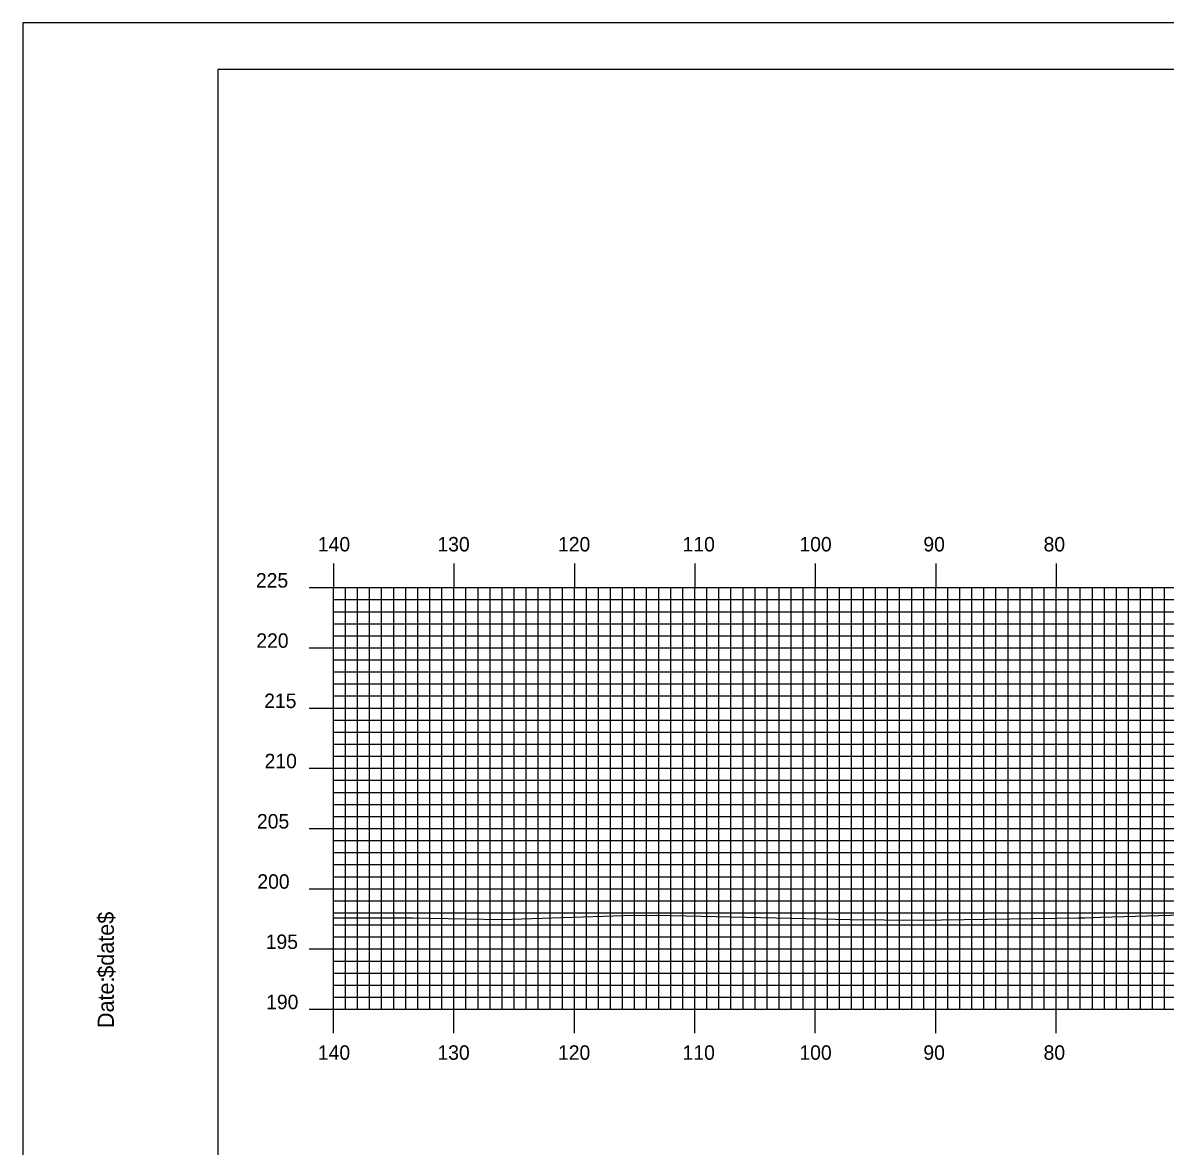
# Model space of a CAD drawing. Extents: x 1811374 to 1811717, y 442591 to 442811.
# Drawn here: x 1811373.6 to 1811468.4, y 442717.3 to 442810.5 of the extents above; entities that cross this region are included whole.
import ezdxf

# ---------------------------------------------------------------- set-up
doc = ezdxf.new("R2010")
doc.units = 0
for name, color, linetype in [('BORDER', 7, 'Continuous'), ('H_V ANNOTATION', 7, 'Continuous'), ('MAJOR', 7, 'Continuous'), ('MINOR', 7, 'Continuous'), ('PLOT BOUNDARY', 7, 'Continuous'), ('S_Roadway_Centerline', 7, 'Continuous')]:
    doc.layers.add(name, color=color, linetype=linetype)

msp = doc.modelspace()

# ---------------------------------------------------------------- linework, layer by layer
at = {"layer": 'BORDER'}
msp.add_lwpolyline([(1811389.803, 442596.665), (1811709.803, 442596.665), (1811709.803, 442806.665), (1811389.803, 442806.665)], close=True, dxfattribs=at)
at = {"layer": 'MAJOR'}
for p, q in [((1811399.403, 442765.669), (1811399.403, 442763.665)), ((1811409.403, 442765.669), (1811409.403, 442763.665)), ((1811419.403, 442765.669), (1811419.403, 442763.665)), ((1811429.403, 442765.669), (1811429.403, 442763.665)), ((1811439.403, 442765.669), (1811439.403, 442763.665)), ((1811449.403, 442765.669), (1811449.403, 442763.665)), ((1811459.403, 442765.669), (1811459.403, 442763.665)), ((1811397.399, 442763.665), (1811399.403, 442763.665)), ((1811399.403, 442763.665), (1811679.403, 442763.665)), ((1811399.403, 442728.665), (1811399.403, 442763.665)), ((1811399.403, 442728.665), (1811399.403, 442763.665)), ((1811399.403, 442763.665), (1811679.403, 442763.665)), ((1811409.403, 442728.665), (1811409.403, 442763.665)), ((1811419.403, 442728.665), (1811419.403, 442763.665)), ((1811429.403, 442728.665), (1811429.403, 442763.665)), ((1811439.403, 442728.665), (1811439.403, 442763.665)), ((1811449.403, 442728.665), (1811449.403, 442763.665)), ((1811459.403, 442728.665), (1811459.403, 442763.665)), ((1811397.399, 442758.665), (1811399.403, 442758.665)), ((1811399.403, 442758.665), (1811679.403, 442758.665)), ((1811397.399, 442753.665), (1811399.403, 442753.665)), ((1811399.403, 442753.665), (1811679.403, 442753.665)), ((1811397.399, 442748.665), (1811399.403, 442748.665)), ((1811399.403, 442748.665), (1811679.403, 442748.665)), ((1811397.399, 442743.665), (1811399.403, 442743.665)), ((1811399.403, 442743.665), (1811679.403, 442743.665)), ((1811397.399, 442738.665), (1811399.403, 442738.665)), ((1811399.403, 442738.665), (1811679.403, 442738.665)), ((1811397.399, 442733.665), (1811399.403, 442733.665)), ((1811399.403, 442733.665), (1811679.403, 442733.665)), ((1811397.399, 442728.665), (1811399.403, 442728.665)), ((1811399.403, 442728.665), (1811679.403, 442728.665)), ((1811399.403, 442728.665), (1811679.403, 442728.665)), ((1811399.403, 442726.661), (1811399.403, 442728.665)), ((1811409.403, 442726.661), (1811409.403, 442728.665)), ((1811419.403, 442726.661), (1811419.403, 442728.665)), ((1811429.403, 442726.661), (1811429.403, 442728.665)), ((1811439.403, 442726.661), (1811439.403, 442728.665)), ((1811449.403, 442726.661), (1811449.403, 442728.665)), ((1811459.403, 442726.661), (1811459.403, 442728.665))]:
    msp.add_line(p, q, dxfattribs=at)
at = {"layer": 'MINOR'}
for p, q in [((1811400.403, 442728.665), (1811400.403, 442763.665)), ((1811401.403, 442728.665), (1811401.403, 442763.665)), ((1811402.403, 442728.665), (1811402.403, 442763.665)), ((1811403.403, 442728.665), (1811403.403, 442763.665)), ((1811404.403, 442728.665), (1811404.403, 442763.665)), ((1811405.403, 442728.665), (1811405.403, 442763.665)), ((1811406.403, 442728.665), (1811406.403, 442763.665)), ((1811407.403, 442728.665), (1811407.403, 442763.665)), ((1811408.403, 442728.665), (1811408.403, 442763.665)), ((1811410.403, 442728.665), (1811410.403, 442763.665)), ((1811411.403, 442728.665), (1811411.403, 442763.665)), ((1811412.403, 442728.665), (1811412.403, 442763.665)), ((1811413.403, 442728.665), (1811413.403, 442763.665)), ((1811414.403, 442728.665), (1811414.403, 442763.665)), ((1811415.403, 442728.665), (1811415.403, 442763.665)), ((1811416.403, 442728.665), (1811416.403, 442763.665)), ((1811417.403, 442728.665), (1811417.403, 442763.665)), ((1811418.403, 442728.665), (1811418.403, 442763.665)), ((1811420.403, 442728.665), (1811420.403, 442763.665)), ((1811421.403, 442728.665), (1811421.403, 442763.665)), ((1811422.403, 442728.665), (1811422.403, 442763.665)), ((1811423.403, 442728.665), (1811423.403, 442763.665)), ((1811424.403, 442728.665), (1811424.403, 442763.665)), ((1811425.403, 442728.665), (1811425.403, 442763.665)), ((1811426.403, 442728.665), (1811426.403, 442763.665)), ((1811427.403, 442728.665), (1811427.403, 442763.665)), ((1811428.403, 442728.665), (1811428.403, 442763.665)), ((1811430.403, 442728.665), (1811430.403, 442763.665)), ((1811431.403, 442728.665), (1811431.403, 442763.665)), ((1811432.403, 442728.665), (1811432.403, 442763.665)), ((1811433.403, 442728.665), (1811433.403, 442763.665)), ((1811434.403, 442728.665), (1811434.403, 442763.665)), ((1811435.403, 442728.665), (1811435.403, 442763.665)), ((1811436.403, 442728.665), (1811436.403, 442763.665)), ((1811437.403, 442728.665), (1811437.403, 442763.665)), ((1811438.403, 442728.665), (1811438.403, 442763.665)), ((1811440.403, 442728.665), (1811440.403, 442763.665)), ((1811441.403, 442728.665), (1811441.403, 442763.665)), ((1811442.403, 442728.665), (1811442.403, 442763.665)), ((1811443.403, 442728.665), (1811443.403, 442763.665)), ((1811444.403, 442728.665), (1811444.403, 442763.665)), ((1811445.403, 442728.665), (1811445.403, 442763.665)), ((1811446.403, 442728.665), (1811446.403, 442763.665)), ((1811447.403, 442728.665), (1811447.403, 442763.665)), ((1811448.403, 442728.665), (1811448.403, 442763.665)), ((1811450.403, 442728.665), (1811450.403, 442763.665)), ((1811451.403, 442728.665), (1811451.403, 442763.665)), ((1811452.403, 442728.665), (1811452.403, 442763.665)), ((1811453.403, 442728.665), (1811453.403, 442763.665)), ((1811454.403, 442728.665), (1811454.403, 442763.665)), ((1811455.403, 442728.665), (1811455.403, 442763.665)), ((1811456.403, 442728.665), (1811456.403, 442763.665)), ((1811457.403, 442728.665), (1811457.403, 442763.665)), ((1811458.403, 442728.665), (1811458.403, 442763.665)), ((1811460.403, 442728.665), (1811460.403, 442763.665)), ((1811461.403, 442728.665), (1811461.403, 442763.665)), ((1811462.403, 442728.665), (1811462.403, 442763.665)), ((1811463.403, 442728.665), (1811463.403, 442763.665)), ((1811464.403, 442728.665), (1811464.403, 442763.665)), ((1811465.403, 442728.665), (1811465.403, 442763.665)), ((1811466.403, 442728.665), (1811466.403, 442763.665)), ((1811467.403, 442728.665), (1811467.403, 442763.665)), ((1811468.403, 442728.665), (1811468.403, 442763.665)), ((1811399.403, 442762.665), (1811679.403, 442762.665)), ((1811399.403, 442762.665), (1811401.407, 442762.665)), ((1811399.403, 442761.665), (1811679.403, 442761.665)), ((1811399.403, 442761.665), (1811401.407, 442761.665)), ((1811399.403, 442760.665), (1811679.403, 442760.665)), ((1811399.403, 442760.665), (1811401.407, 442760.665)), ((1811399.403, 442759.665), (1811679.403, 442759.665)), ((1811399.403, 442759.665), (1811401.407, 442759.665)), ((1811399.403, 442757.665), (1811679.403, 442757.665)), ((1811399.403, 442757.665), (1811401.407, 442757.665)), ((1811399.403, 442756.665), (1811679.403, 442756.665)), ((1811399.403, 442756.665), (1811401.407, 442756.665)), ((1811399.403, 442755.665), (1811679.403, 442755.665)), ((1811399.403, 442755.665), (1811401.407, 442755.665)), ((1811399.403, 442754.665), (1811679.403, 442754.665)), ((1811399.403, 442754.665), (1811401.407, 442754.665)), ((1811399.403, 442752.665), (1811679.403, 442752.665)), ((1811399.403, 442752.665), (1811401.407, 442752.665)), ((1811399.403, 442751.665), (1811679.403, 442751.665)), ((1811399.403, 442751.665), (1811401.407, 442751.665)), ((1811399.403, 442750.665), (1811679.403, 442750.665)), ((1811399.403, 442750.665), (1811401.407, 442750.665)), ((1811399.403, 442749.665), (1811679.403, 442749.665)), ((1811399.403, 442749.665), (1811401.407, 442749.665)), ((1811399.403, 442747.665), (1811679.403, 442747.665)), ((1811399.403, 442747.665), (1811401.407, 442747.665)), ((1811399.403, 442746.665), (1811679.403, 442746.665)), ((1811399.403, 442746.665), (1811401.407, 442746.665)), ((1811399.403, 442745.665), (1811679.403, 442745.665)), ((1811399.403, 442745.665), (1811401.407, 442745.665)), ((1811399.403, 442744.665), (1811679.403, 442744.665)), ((1811399.403, 442744.665), (1811401.407, 442744.665)), ((1811399.403, 442742.665), (1811679.403, 442742.665)), ((1811399.403, 442742.665), (1811401.407, 442742.665)), ((1811399.403, 442741.665), (1811679.403, 442741.665)), ((1811399.403, 442741.665), (1811401.407, 442741.665)), ((1811399.403, 442740.665), (1811679.403, 442740.665)), ((1811399.403, 442740.665), (1811401.407, 442740.665)), ((1811399.403, 442739.665), (1811679.403, 442739.665)), ((1811399.403, 442739.665), (1811401.407, 442739.665)), ((1811399.403, 442737.665), (1811679.403, 442737.665)), ((1811399.403, 442737.665), (1811401.407, 442737.665)), ((1811399.403, 442736.665), (1811679.403, 442736.665)), ((1811399.403, 442736.665), (1811401.407, 442736.665)), ((1811399.403, 442735.665), (1811679.403, 442735.665)), ((1811399.403, 442735.665), (1811401.407, 442735.665)), ((1811399.403, 442734.665), (1811679.403, 442734.665)), ((1811399.403, 442734.665), (1811401.407, 442734.665)), ((1811399.403, 442732.665), (1811679.403, 442732.665)), ((1811399.403, 442732.665), (1811401.407, 442732.665)), ((1811399.403, 442731.665), (1811679.403, 442731.665)), ((1811399.403, 442731.665), (1811401.407, 442731.665)), ((1811399.403, 442730.665), (1811679.403, 442730.665)), ((1811399.403, 442730.665), (1811401.407, 442730.665)), ((1811399.403, 442729.665), (1811679.403, 442729.665)), ((1811399.403, 442729.665), (1811401.407, 442729.665))]:
    msp.add_line(p, q, dxfattribs=at)
at = {"layer": 'PLOT BOUNDARY'}
msp.add_lwpolyline([(1811373.616, 442590.547), (1811713.616, 442590.547), (1811713.616, 442810.547), (1811373.616, 442810.547)], close=True, dxfattribs=at)
at = {"layer": 'S_Roadway_Centerline'}
msp.add_lwpolyline([(1811399.403, 442736.257), (1811405.995, 442736.26), (1811413.355, 442736.099), (1811423.478, 442736.45), (1811426.232, 442736.464), (1811442.294, 442736.112), (1811447.967, 442736.064), (1811461.247, 442736.246), (1811461.788, 442736.254), (1811463.066, 442736.301), (1811481.413, 442736.832)], dxfattribs=at)

# ---------------------------------------------------------------- texts
at = {"layer": 'BORDER'}
for s, p in [('$date$', (1811381.173, 442731.275)), ('Date:', (1811381.173, 442727.099))]:
    msp.add_text(s, height=1.3392, rotation=90, dxfattribs=at).set_placement(p)
at = {"layer": 'H_V ANNOTATION'}
for s, p in [('140', (1811398.108, 442766.665)), ('130', (1811408.033, 442766.665)), ('120', (1811418.043, 442766.665)), ('110', (1811428.386, 442766.665)), ('100', (1811438.086, 442766.665)), ('90', (1811448.375, 442766.665)), ('80', (1811458.354, 442766.665)), ('225', (1811392.966, 442763.665)), ('220', (1811392.998, 442758.665)), ('215', (1811393.652, 442753.665)), ('210', (1811393.684, 442748.665)), ('205', (1811393.052, 442743.665)), ('200', (1811393.084, 442738.665)), ('195', (1811393.78, 442733.665)), ('190', (1811393.813, 442728.665)), ('140', (1811398.108, 442724.465)), ('130', (1811408.033, 442724.465)), ('120', (1811418.043, 442724.465)), ('110', (1811428.386, 442724.465)), ('100', (1811438.086, 442724.465)), ('90', (1811448.375, 442724.465)), ('80', (1811458.354, 442724.465))]:
    msp.add_text(s, height=1.2, dxfattribs=at).set_placement(p)
at = {"layer": 'MAJOR'}
msp.add_text('-', height=0.012, dxfattribs=at).set_placement((1811399.394, 442728.665))

doc.saveas('drawing.dxf')
